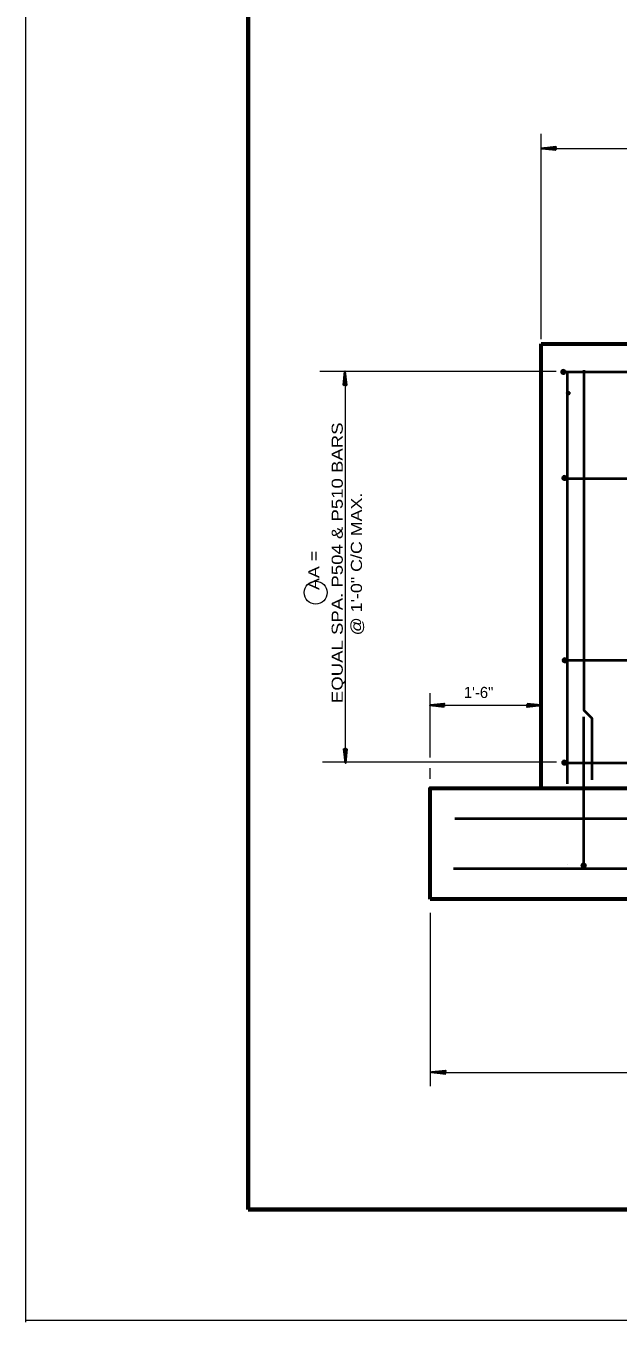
# Model space of a CAD drawing. Extents: x 14.14 to 17.34, y -1.61 to 0.38.
# Drawn here: x 14.143 to 14.587, y -1.606 to -0.633 of the extents above; entities that cross this region are included whole.
import ezdxf
from ezdxf.enums import TextEntityAlignment as Align

# ---------------------------------------------------------------- set-up
doc = ezdxf.new("R2010")
doc.units = 0
doc.header["$LTSCALE"] = 0.0033
doc.header["$PDMODE"] = 32
doc.header["$PDSIZE"] = 0.00165
doc.layers.add('1', color=7, linetype='Continuous', lineweight=40)

msp = doc.modelspace()

# ---------------------------------------------------------------- linework, layer by layer
at = {"layer": '1', "lineweight": 13}
for p, q in [((14.142583, -1.605917), (14.142583, 0.382333)), ((14.52925, -0.86825), (14.52925, -0.714)), ((14.529417, -0.725083), (15.111917, -0.725083)), ((14.5405, -0.892333), (14.36325, -0.892333)), ((14.382417, -1.185083), (14.382417, -0.8985)), ((14.445917, -1.18225), (14.445917, -1.133833)), ((14.445833, -1.143), (14.52875, -1.143)), ((14.540667, -1.18575), (14.365083, -1.18575)), ((14.445917, -1.198083), (14.445917, -1.19025)), ((14.54875, -1.2625), (14.54875, -1.262583)), ((14.445917, -1.298667), (14.445917, -1.428833)), ((14.447083, -1.4185), (14.830083, -1.4185)), ((17.339333, -1.60475), (14.142583, -1.60475))]:
    msp.add_line(p, q, dxfattribs=at)
at = {"layer": '1', "lineweight": 35}
for p, q in [((14.540333, -0.725083), (14.52975, -0.725083)), ((14.540083, -0.725917), (14.53225, -0.724917)), ((14.540083, -0.725917), (14.53225, -0.725083)), ((14.540083, -0.726083), (14.53225, -0.725167)), ((14.540083, -0.726083), (14.53225, -0.725167)), ((14.540083, -0.726), (14.53225, -0.725167)), ((14.540083, -0.724), (14.53275, -0.724833)), ((14.540083, -0.724167), (14.53275, -0.724917)), ((14.540083, -0.72425), (14.53275, -0.725083)), ((14.540167, -0.724417), (14.532833, -0.725167)), ((14.380917, -0.902583), (14.381833, -0.89475)), ((14.380917, -0.902583), (14.381833, -0.89475)), ((14.381, -0.902583), (14.381833, -0.89475)), ((14.381083, -0.902583), (14.381917, -0.89475)), ((14.381083, -0.902583), (14.382083, -0.89475)), ((14.381917, -0.902833), (14.381917, -0.89225)), ((14.382583, -0.902667), (14.381833, -0.895333)), ((14.38275, -0.902583), (14.381917, -0.89525)), ((14.382833, -0.902583), (14.382083, -0.89525)), ((14.383, -0.902583), (14.382167, -0.89525)), ((14.4565, -1.143), (14.445917, -1.143)), ((14.45625, -1.143833), (14.448417, -1.142833)), ((14.45625, -1.143833), (14.448417, -1.143)), ((14.45625, -1.144), (14.448417, -1.143083)), ((14.45625, -1.144), (14.448417, -1.143083)), ((14.45625, -1.143917), (14.448417, -1.143083)), ((14.45625, -1.141917), (14.448917, -1.14275)), ((14.45625, -1.142083), (14.448917, -1.142833)), ((14.45625, -1.142167), (14.448917, -1.143)), ((14.456333, -1.142333), (14.449, -1.143083)), ((14.518583, -1.143), (14.529167, -1.143)), ((14.51875, -1.143667), (14.526083, -1.142917)), ((14.518833, -1.142), (14.526667, -1.142917)), ((14.518833, -1.142), (14.526667, -1.142917)), ((14.518833, -1.142083), (14.526667, -1.142917)), ((14.518833, -1.142167), (14.526667, -1.143)), ((14.518833, -1.142167), (14.526667, -1.143167)), ((14.518833, -1.143833), (14.526167, -1.143)), ((14.518833, -1.143917), (14.526167, -1.143167)), ((14.518833, -1.144083), (14.526167, -1.14325)), ((14.381333, -1.175917), (14.382167, -1.18325)), ((14.3815, -1.175917), (14.38225, -1.18325)), ((14.381583, -1.175917), (14.382417, -1.18325)), ((14.38175, -1.175833), (14.3825, -1.183167)), ((14.38325, -1.175917), (14.38225, -1.18375)), ((14.382417, -1.175667), (14.382417, -1.18625)), ((14.38325, -1.175917), (14.382417, -1.18375)), ((14.383417, -1.175917), (14.3825, -1.18375)), ((14.383417, -1.175917), (14.3825, -1.18375)), ((14.383333, -1.175917), (14.3825, -1.18375)), ((14.457583, -1.418417), (14.447, -1.418417)), ((14.457333, -1.41925), (14.4495, -1.41825)), ((14.457333, -1.41925), (14.4495, -1.418417)), ((14.457333, -1.419417), (14.4495, -1.4185)), ((14.457333, -1.419417), (14.4495, -1.4185)), ((14.457333, -1.419333), (14.4495, -1.4185)), ((14.457333, -1.417333), (14.45, -1.418167)), ((14.457333, -1.4175), (14.45, -1.41825)), ((14.457333, -1.417583), (14.45, -1.418417)), ((14.457417, -1.41775), (14.450083, -1.4185))]:
    msp.add_line(p, q, dxfattribs=at)
at = {"layer": '1', "lineweight": 60}
for p, q in [((14.52925, -0.87175), (14.80725, -0.87175)), ((14.791917, -1.288417), (14.445917, -1.288417))]:
    msp.add_line(p, q, dxfattribs=at)
at = {"layer": '1'}
for p, q in [((14.54475, -0.8935), (14.544833, -0.892)), ((14.546833, -0.893333), (14.544833, -0.892917)), ((14.546833, -0.893417), (14.544833, -0.893)), ((14.546833, -0.8935), (14.544833, -0.893167)), ((14.546833, -0.893583), (14.544833, -0.89325)), ((14.54675, -0.89375), (14.544833, -0.893417)), ((14.544917, -0.8935), (14.545, -0.892)), ((14.546917, -0.893), (14.544917, -0.892583)), ((14.546917, -0.893083), (14.544917, -0.89275)), ((14.546833, -0.893167), (14.544917, -0.892833)), ((14.545, -0.8935), (14.545083, -0.892)), ((14.547, -0.892417), (14.545, -0.892083)), ((14.547, -0.892667), (14.545, -0.89225)), ((14.546917, -0.892833), (14.545, -0.892417)), ((14.546917, -0.892917), (14.545, -0.8925)), ((14.547083, -0.892167), (14.545083, -0.891833)), ((14.547, -0.89225), (14.545083, -0.891917)), ((14.545083, -0.8935), (14.545167, -0.892)), ((14.547, -0.892333), (14.545083, -0.892)), ((14.545167, -0.8935), (14.54525, -0.892)), ((14.54525, -0.8935), (14.545333, -0.892)), ((14.545333, -0.8935), (14.545417, -0.892)), ((14.545417, -0.8935), (14.5455, -0.892)), ((14.545417, -0.8935), (14.5455, -0.892)), ((14.5455, -0.8935), (14.545667, -0.892)), ((14.545667, -0.8935), (14.545833, -0.892)), ((14.545833, -0.893583), (14.545917, -0.892083)), ((14.545917, -0.893583), (14.546, -0.892083)), ((14.546, -0.893583), (14.546083, -0.892083)), ((14.546083, -0.893583), (14.546167, -0.892083)), ((14.546167, -0.893583), (14.54625, -0.892083)), ((14.54625, -0.893583), (14.546333, -0.892083)), ((14.546333, -0.893583), (14.546417, -0.892083)), ((14.5465, -0.893583), (14.546583, -0.892083)), ((14.546583, -0.893583), (14.546667, -0.892083)), ((14.546667, -0.893583), (14.54675, -0.892083)), ((14.54675, -0.893583), (14.546833, -0.892083)), ((14.546833, -0.893583), (14.546917, -0.892083)), ((14.547333, -0.89275), (14.65175, -0.89275)), ((14.54875, -0.892833), (14.54875, -1.202)), ((14.545583, -0.973083), (14.545667, -0.971583)), ((14.547667, -0.972917), (14.545667, -0.9725)), ((14.547667, -0.973), (14.545667, -0.972583)), ((14.547667, -0.973083), (14.545667, -0.97275)), ((14.547667, -0.973167), (14.545667, -0.972833)), ((14.54575, -0.973083), (14.545833, -0.971583)), ((14.54775, -0.972583), (14.54575, -0.972167)), ((14.54775, -0.972667), (14.54575, -0.972333)), ((14.547667, -0.97275), (14.54575, -0.972417)), ((14.545833, -0.973083), (14.545917, -0.971583)), ((14.547833, -0.972), (14.545833, -0.971667)), ((14.547833, -0.97225), (14.545833, -0.971833)), ((14.54775, -0.972417), (14.545833, -0.972)), ((14.54775, -0.9725), (14.545833, -0.972083)), ((14.547917, -0.97175), (14.545917, -0.971417)), ((14.547833, -0.971833), (14.545917, -0.9715)), ((14.545917, -0.973083), (14.546, -0.971583)), ((14.547833, -0.971917), (14.545917, -0.971583)), ((14.546, -0.973083), (14.546083, -0.971583)), ((14.546083, -0.973083), (14.546167, -0.971583)), ((14.546167, -0.973083), (14.54625, -0.971583)), ((14.54625, -0.973083), (14.546333, -0.971583)), ((14.54625, -0.973083), (14.546333, -0.971583)), ((14.546333, -0.973083), (14.5465, -0.971583)), ((14.5465, -0.973083), (14.546667, -0.971583)), ((14.546667, -0.973167), (14.54675, -0.971667)), ((14.54675, -0.973167), (14.546833, -0.971667)), ((14.546833, -0.973167), (14.546917, -0.971667)), ((14.546917, -0.973167), (14.547, -0.971667)), ((14.547, -0.973167), (14.547083, -0.971667)), ((14.547083, -0.973167), (14.547167, -0.971667)), ((14.547167, -0.973167), (14.54725, -0.971667)), ((14.547333, -0.973167), (14.547417, -0.971667)), ((14.547417, -0.973167), (14.5475, -0.971667)), ((14.5475, -0.973167), (14.547583, -0.971667)), ((14.547583, -0.973167), (14.547667, -0.971667)), ((14.547667, -0.973167), (14.54775, -0.971667)), ((14.547917, -0.972833), (14.654083, -0.972833)), ((14.547583, -0.973333), (14.545667, -0.973)), ((14.545833, -1.109917), (14.545917, -1.108417)), ((14.546, -1.109917), (14.546083, -1.108417)), ((14.548, -1.109417), (14.546, -1.109)), ((14.546083, -1.109917), (14.546167, -1.108417)), ((14.548083, -1.108833), (14.546083, -1.1085)), ((14.548083, -1.109083), (14.546083, -1.108667)), ((14.548, -1.10925), (14.546083, -1.108833)), ((14.548, -1.109333), (14.546083, -1.108917)), ((14.548167, -1.108583), (14.546167, -1.10825)), ((14.548083, -1.108667), (14.546167, -1.108333)), ((14.546167, -1.109917), (14.54625, -1.108417)), ((14.548083, -1.10875), (14.546167, -1.108417)), ((14.54625, -1.109917), (14.546333, -1.108417)), ((14.546333, -1.109917), (14.546417, -1.108417)), ((14.546417, -1.109917), (14.5465, -1.108417)), ((14.5465, -1.109917), (14.546583, -1.108417)), ((14.5465, -1.109917), (14.546583, -1.108417)), ((14.546583, -1.109917), (14.54675, -1.108417)), ((14.54675, -1.109917), (14.546917, -1.108417)), ((14.546917, -1.11), (14.547, -1.1085)), ((14.547, -1.11), (14.547083, -1.1085)), ((14.547083, -1.11), (14.547167, -1.1085)), ((14.547167, -1.11), (14.54725, -1.1085)), ((14.54725, -1.11), (14.547333, -1.1085)), ((14.547333, -1.11), (14.547417, -1.1085)), ((14.547417, -1.11), (14.5475, -1.1085)), ((14.547583, -1.11), (14.547667, -1.1085)), ((14.547667, -1.11), (14.54775, -1.1085)), ((14.54775, -1.11), (14.547833, -1.1085)), ((14.547833, -1.11), (14.547917, -1.1085)), ((14.547917, -1.11), (14.548, -1.1085)), ((14.547917, -1.10975), (14.545917, -1.109333)), ((14.547917, -1.109833), (14.545917, -1.109417)), ((14.547917, -1.109917), (14.545917, -1.109583)), ((14.547917, -1.11), (14.545917, -1.109667)), ((14.547833, -1.110167), (14.545917, -1.109833)), ((14.548, -1.1095), (14.546, -1.109167)), ((14.547917, -1.109583), (14.546, -1.10925)), ((14.548083, -1.109167), (14.655417, -1.109167)), ((14.560917, -1.151583), (14.560917, -1.263417)), ((14.5455, -1.18675), (14.545583, -1.18525)), ((14.547583, -1.186583), (14.545583, -1.186167)), ((14.547583, -1.186667), (14.545583, -1.18625)), ((14.547583, -1.18675), (14.545583, -1.186417)), ((14.547583, -1.186833), (14.545583, -1.1865)), ((14.5475, -1.187), (14.545583, -1.186667)), ((14.545667, -1.18675), (14.54575, -1.18525)), ((14.547667, -1.18625), (14.545667, -1.185833)), ((14.547667, -1.186333), (14.545667, -1.186)), ((14.547583, -1.186417), (14.545667, -1.186083)), ((14.54575, -1.18675), (14.545833, -1.18525)), ((14.54775, -1.185667), (14.54575, -1.185333)), ((14.54775, -1.185917), (14.54575, -1.1855)), ((14.547667, -1.186083), (14.54575, -1.185667)), ((14.547667, -1.186167), (14.54575, -1.18575)), ((14.547833, -1.185417), (14.545833, -1.185083)), ((14.54775, -1.1855), (14.545833, -1.185167)), ((14.545833, -1.18675), (14.545917, -1.18525)), ((14.54775, -1.185583), (14.545833, -1.18525)), ((14.545917, -1.18675), (14.546, -1.18525)), ((14.546, -1.18675), (14.546083, -1.18525)), ((14.546083, -1.18675), (14.546167, -1.18525)), ((14.546167, -1.18675), (14.54625, -1.18525)), ((14.546167, -1.18675), (14.54625, -1.18525)), ((14.54625, -1.18675), (14.546417, -1.18525)), ((14.546417, -1.18675), (14.546583, -1.18525)), ((14.546583, -1.186833), (14.546667, -1.185333)), ((14.546667, -1.186833), (14.54675, -1.185333)), ((14.54675, -1.186833), (14.546833, -1.185333)), ((14.546833, -1.186833), (14.546917, -1.185333)), ((14.546917, -1.186833), (14.547, -1.185333)), ((14.547, -1.186833), (14.547083, -1.185333)), ((14.547083, -1.186833), (14.547167, -1.185333)), ((14.54725, -1.186833), (14.547333, -1.185333)), ((14.547333, -1.186833), (14.547417, -1.185333)), ((14.547417, -1.186833), (14.5475, -1.185333)), ((14.5475, -1.186833), (14.547583, -1.185333)), ((14.547583, -1.186833), (14.547667, -1.185333)), ((14.549167, -1.186167), (14.656, -1.186167)), ((14.560417, -1.262083), (14.560083, -1.264083)), ((14.5605, -1.262167), (14.560167, -1.264083)), ((14.560583, -1.262167), (14.56025, -1.264083)), ((14.56175, -1.2635), (14.56025, -1.263333)), ((14.56175, -1.263667), (14.56025, -1.2635)), ((14.56175, -1.26375), (14.56025, -1.263667)), ((14.56175, -1.26375), (14.56025, -1.263667)), ((14.56175, -1.263833), (14.56025, -1.26375)), ((14.56175, -1.263917), (14.56025, -1.263833)), ((14.56175, -1.264), (14.56025, -1.263917)), ((14.56175, -1.264083), (14.56025, -1.264)), ((14.56175, -1.264167), (14.56025, -1.264083)), ((14.56175, -1.26425), (14.56025, -1.264167)), ((14.56175, -1.264417), (14.56025, -1.264333)), ((14.560667, -1.262167), (14.560333, -1.264167)), ((14.561833, -1.262333), (14.560333, -1.26225)), ((14.561833, -1.262417), (14.560333, -1.262333)), ((14.561833, -1.2625), (14.560333, -1.262417)), ((14.561833, -1.262583), (14.560333, -1.2625)), ((14.561833, -1.262667), (14.560333, -1.262583)), ((14.561833, -1.262833), (14.560333, -1.26275)), ((14.561833, -1.262917), (14.560333, -1.262833)), ((14.561833, -1.263), (14.560333, -1.262917)), ((14.561833, -1.263083), (14.560333, -1.263)), ((14.561833, -1.263167), (14.560333, -1.263083)), ((14.561833, -1.26325), (14.560333, -1.263167)), ((14.561833, -1.263333), (14.560333, -1.26325)), ((14.560917, -1.262167), (14.5605, -1.264167)), ((14.561083, -1.26225), (14.560667, -1.264167)), ((14.561167, -1.26225), (14.56075, -1.264167)), ((14.56125, -1.26225), (14.560833, -1.26425)), ((14.561333, -1.26225), (14.561, -1.26425)), ((14.561417, -1.262333), (14.561083, -1.26425)), ((14.561583, -1.262333), (14.561167, -1.264333)), ((14.561667, -1.262333), (14.56125, -1.264333)), ((14.56175, -1.262333), (14.561417, -1.264333)), ((14.561833, -1.262333), (14.5615, -1.264333)), ((14.562, -1.262417), (14.561667, -1.264333))]:
    msp.add_line(p, q, dxfattribs=at)
at = {"layer": '1', "lineweight": 70}
msp.add_line((14.309333, -1.521417), (17.256, -1.521417), dxfattribs=at)
msp.add_lwpolyline([(17.256, -1.521417), (17.256, 0.298667), (14.309333, 0.298667), (14.309333, -1.521417)], dxfattribs=at)
at = {"layer": '1', "lineweight": 35}
for points in [[(14.540333, -0.726167), (14.52975, -0.725083), (14.540333, -0.723917), (14.53975, -0.725083)], [(14.539583, -0.725167), (14.534917, -0.72525), (14.534917, -0.725167), (14.535833, -0.725167), (14.539583, -0.72525), (14.536583, -0.725333), (14.53975, -0.725417), (14.5375, -0.7255), (14.53975, -0.725583), (14.53625, -0.725333), (14.531583, -0.725167), (14.5325, -0.724917), (14.53125, -0.724917), (14.539583, -0.724917), (14.537167, -0.72475), (14.53975, -0.72475), (14.534417, -0.725167), (14.53975, -0.7245)], [(14.380833, -0.902833), (14.381917, -0.89225), (14.383083, -0.902833), (14.381917, -0.90225)], [(14.381833, -0.902083), (14.38175, -0.897417), (14.381833, -0.897417), (14.381833, -0.898333), (14.38175, -0.902083), (14.381667, -0.899083), (14.381583, -0.90225), (14.3815, -0.9), (14.381417, -0.90225), (14.381667, -0.89875), (14.381833, -0.894083), (14.382083, -0.895), (14.382083, -0.89375), (14.382083, -0.902083), (14.38225, -0.899667), (14.38225, -0.90225), (14.381833, -0.896917), (14.3825, -0.90225)], [(14.4565, -1.144083), (14.445917, -1.143), (14.4565, -1.141833), (14.455917, -1.143)], [(14.45575, -1.143083), (14.451083, -1.143167), (14.451083, -1.143083), (14.452, -1.143083), (14.45575, -1.143167), (14.45275, -1.14325), (14.455917, -1.143333), (14.453667, -1.143417), (14.455917, -1.1435), (14.452417, -1.14325), (14.44775, -1.143083), (14.448667, -1.142833), (14.447417, -1.142833), (14.45575, -1.142833), (14.453333, -1.142667), (14.455917, -1.142667), (14.450583, -1.143083), (14.455917, -1.142417)], [(14.518583, -1.141917), (14.529167, -1.143), (14.518583, -1.144167), (14.519167, -1.143)], [(14.519333, -1.142917), (14.524, -1.142833), (14.524, -1.142917), (14.523083, -1.142917), (14.519333, -1.142833), (14.522333, -1.14275), (14.519167, -1.142667), (14.521417, -1.142583), (14.519167, -1.1425), (14.522667, -1.14275), (14.527333, -1.142917), (14.526417, -1.143167), (14.527667, -1.143167), (14.519333, -1.143167), (14.52175, -1.143333), (14.519167, -1.143333), (14.5245, -1.142917), (14.519167, -1.143583)], [(14.3835, -1.175667), (14.382417, -1.18625), (14.38125, -1.175667), (14.382417, -1.17625)], [(14.3825, -1.176417), (14.382583, -1.181083), (14.3825, -1.181083), (14.3825, -1.180167), (14.382583, -1.176417), (14.382667, -1.179417), (14.38275, -1.17625), (14.382833, -1.1785), (14.382917, -1.17625), (14.382667, -1.17975), (14.3825, -1.184417), (14.38225, -1.1835), (14.38225, -1.18475), (14.38225, -1.176417), (14.382083, -1.178833), (14.382083, -1.17625), (14.3825, -1.181583), (14.381833, -1.17625)], [(14.457583, -1.4195), (14.447, -1.418417), (14.457583, -1.41725), (14.457, -1.418417)], [(14.456833, -1.4185), (14.452167, -1.418583), (14.452167, -1.4185), (14.453083, -1.4185), (14.456833, -1.418583), (14.453833, -1.418667), (14.457, -1.41875), (14.45475, -1.418833), (14.457, -1.418917), (14.4535, -1.418667), (14.448833, -1.4185), (14.44975, -1.41825), (14.4485, -1.41825), (14.456833, -1.41825), (14.454417, -1.418083), (14.457, -1.418083), (14.451667, -1.4185), (14.457, -1.417833)]]:
    msp.add_lwpolyline(points, close=True, dxfattribs=at)
for points in [[(14.539583, -0.725167), (14.54, -0.725917), (14.53975, -0.725667), (14.539583, -0.725333), (14.539333, -0.725417), (14.5395, -0.72575), (14.539667, -0.725), (14.539833, -0.7245), (14.540083, -0.724083)], [(14.381833, -0.902083), (14.381083, -0.9025), (14.381333, -0.90225), (14.381667, -0.902083), (14.381583, -0.901833), (14.38125, -0.902), (14.382, -0.902167), (14.3825, -0.902333), (14.382917, -0.902583)], [(14.45575, -1.143083), (14.456167, -1.143833), (14.455917, -1.143583), (14.45575, -1.14325), (14.4555, -1.143333), (14.455667, -1.143667), (14.455833, -1.142917), (14.456, -1.142417), (14.45625, -1.142)], [(14.519333, -1.142917), (14.518917, -1.142167), (14.519167, -1.142417), (14.519333, -1.14275), (14.519583, -1.142667), (14.519417, -1.142333), (14.51925, -1.143083), (14.519083, -1.143583), (14.518833, -1.144)], [(14.3825, -1.176417), (14.38325, -1.176), (14.383, -1.17625), (14.382667, -1.176417), (14.38275, -1.176667), (14.383083, -1.1765), (14.382333, -1.176333), (14.381833, -1.176167), (14.381417, -1.175917)], [(14.456833, -1.4185), (14.45725, -1.41925), (14.457, -1.419), (14.456833, -1.418667), (14.456583, -1.41875), (14.45675, -1.419083), (14.456917, -1.418333), (14.457083, -1.417833), (14.457333, -1.417417)]]:
    msp.add_lwpolyline(points, dxfattribs=at)
at = {"layer": '1', "lineweight": 60}
for points in [[(14.445917, -1.288417), (14.445917, -1.205083), (14.52925, -1.205083), (14.52925, -0.87175)], [(14.52925, -1.205083), (14.772417, -1.205083), (15.112583, -1.205083)]]:
    msp.add_lwpolyline(points, dxfattribs=at)
at = {"layer": '1'}
for points in [[(14.54725, -0.89275), (14.544667, -0.893083), (14.547, -0.893583), (14.544667, -0.8925), (14.547083, -0.892083), (14.545083, -0.89175), (14.545083, -0.893833), (14.546, -0.8915), (14.54575, -0.894083), (14.54675, -0.89175), (14.546417, -0.894083), (14.545583, -0.8915), (14.547167, -0.89325), (14.54475, -0.893417), (14.546417, -0.891583), (14.545333, -0.894), (14.547, -0.893583), (14.547083, -0.892083), (14.546, -0.8915), (14.545083, -0.89175), (14.544667, -0.8925), (14.54475, -0.893417), (14.545333, -0.894), (14.546, -0.892917), (14.544833, -0.892), (14.54675, -0.89175), (14.546, -0.892917), (14.547083, -0.893417), (14.546083, -0.894083), (14.546, -0.893), (14.545167, -0.89175), (14.547167, -0.893), (14.545833, -0.893333), (14.545083, -0.893833)], [(14.56125, -0.891417), (14.56125, -1.146667), (14.567167, -1.152583), (14.567167, -1.198833)], [(14.548083, -0.972333), (14.5455, -0.972667), (14.547833, -0.973167), (14.5455, -0.972083), (14.547917, -0.971667), (14.545917, -0.971333), (14.545917, -0.973417), (14.546833, -0.971083), (14.546583, -0.973667), (14.547583, -0.971333), (14.54725, -0.973667), (14.546417, -0.971083), (14.548, -0.972833), (14.545583, -0.973), (14.54725, -0.971167), (14.546167, -0.973583), (14.547833, -0.973167), (14.547917, -0.971667), (14.546833, -0.971083), (14.545917, -0.971333), (14.5455, -0.972083), (14.545583, -0.973), (14.546167, -0.973583), (14.546833, -0.9725), (14.545667, -0.971583), (14.547583, -0.971333), (14.546833, -0.9725), (14.547917, -0.973), (14.546917, -0.973667), (14.546833, -0.972583), (14.546, -0.971333), (14.548, -0.972583), (14.546667, -0.972917), (14.545917, -0.973417)], [(14.548333, -1.109167), (14.54575, -1.1095), (14.548083, -1.11), (14.54575, -1.108917), (14.548167, -1.1085), (14.546167, -1.108167), (14.546167, -1.11025), (14.547083, -1.107917), (14.546833, -1.1105), (14.547833, -1.108167), (14.5475, -1.1105), (14.546667, -1.107917), (14.54825, -1.109667), (14.545833, -1.109833), (14.5475, -1.108), (14.546417, -1.110417), (14.548083, -1.11), (14.548167, -1.1085), (14.547083, -1.107917), (14.546167, -1.108167), (14.54575, -1.108917), (14.545833, -1.109833), (14.546417, -1.110417), (14.547083, -1.109333), (14.545917, -1.108417), (14.547833, -1.108167), (14.547083, -1.109333), (14.548167, -1.109833), (14.547167, -1.1105), (14.547083, -1.109417), (14.54625, -1.108167), (14.54825, -1.109417), (14.546917, -1.10975), (14.546167, -1.11025)], [(14.548, -1.186), (14.545417, -1.186333), (14.54775, -1.186833), (14.545417, -1.18575), (14.547833, -1.185333), (14.545833, -1.185), (14.545833, -1.187083), (14.54675, -1.18475), (14.5465, -1.187333), (14.5475, -1.185), (14.547167, -1.187333), (14.546333, -1.18475), (14.547917, -1.1865), (14.5455, -1.186667), (14.547167, -1.184833), (14.546083, -1.18725), (14.54775, -1.186833), (14.547833, -1.185333), (14.54675, -1.18475), (14.545833, -1.185), (14.545417, -1.18575), (14.5455, -1.186667), (14.546083, -1.18725), (14.54675, -1.186167), (14.545583, -1.18525), (14.5475, -1.185), (14.54675, -1.186167), (14.547833, -1.186667), (14.546833, -1.187333), (14.54675, -1.18625), (14.545917, -1.185), (14.547917, -1.18625), (14.546583, -1.186583), (14.545833, -1.187083)], [(14.309333, -1.521417), (16.671, -1.521417), (16.671, -1.196333), (17.256, -1.196333)], [(14.464333, -1.228), (14.772417, -1.228), (14.834167, -1.228)], [(14.561, -1.261917), (14.561333, -1.2645), (14.561833, -1.262167), (14.56075, -1.2645), (14.560333, -1.262083), (14.56, -1.264083), (14.562083, -1.264083), (14.55975, -1.263167), (14.562333, -1.263417), (14.56, -1.262417), (14.562333, -1.26275), (14.55975, -1.263583), (14.5615, -1.262), (14.561667, -1.264417), (14.559833, -1.26275), (14.56225, -1.263833), (14.561833, -1.262167), (14.560333, -1.262083), (14.55975, -1.263167), (14.56, -1.264083), (14.56075, -1.2645), (14.561667, -1.264417), (14.56225, -1.263833), (14.561167, -1.263167), (14.56025, -1.264333), (14.56, -1.262417), (14.561167, -1.263167), (14.561667, -1.262083), (14.562333, -1.263083), (14.56125, -1.263167), (14.56, -1.264), (14.56125, -1.262), (14.561583, -1.263333), (14.562083, -1.264083)], [(14.4635, -1.265417), (14.7725, -1.265417), (14.834417, -1.265417)]]:
    msp.add_lwpolyline(points, dxfattribs=at)
for centre in [(14.545917, -0.8928), (14.54675, -0.972383), (14.547, -1.109217), (14.546667, -1.18605), (14.56105, -1.26325)]:
    msp.add_circle(centre, 0.00132, dxfattribs=at)
at = {"layer": '1', "lineweight": 13}
msp.add_circle((14.36, -1.058417), 0.008584, dxfattribs=at)
at = {"layer": '1'}
msp.add_point((14.549667, -0.90875), dxfattribs=at)

# ---------------------------------------------------------------- texts
for s, width, p in [('EQUAL SPA. P504 & P510 BARS', 1.25, (14.380333, -1.141333)), ('@ 1\'-0" C/C MAX.', 1.2, (14.39475, -1.0905))]:
    msp.add_text(s, height=0.008334, rotation=90, dxfattribs=dict(at, width=width)).set_placement(p)
at = {"layer": '1', "width": 1.2}
msp.add_text('AA =      ', height=0.008334, rotation=90, dxfattribs=at).set_placement((14.36275, -1.030625), align=Align.CENTER)
at = {"layer": '1'}
msp.add_text('1\'-6"', height=0.008334, dxfattribs=at).set_placement((14.471167, -1.1375))

doc.saveas('drawing.dxf')
